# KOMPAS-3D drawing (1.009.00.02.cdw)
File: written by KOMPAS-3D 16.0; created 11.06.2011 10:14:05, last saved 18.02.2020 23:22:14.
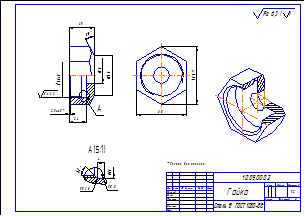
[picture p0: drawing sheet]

Sheet 1: A3, landscape

Title block, sheet 1: name: Гайка; designation: 1.009.00.02; material: Сталь 15  ГОСТ 1050-88; scale: 1:2; sheets: 1; sheet format: A4; stored path: C:\Users\Catonok\Desktop\Гайка.cdw

Views: Вид 1, Вид 2, Вид 3, Спереди 1, Вид по стрелке 4, Вид 7, Вид 8
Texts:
  Catonok
  *Размер для справок.
  Стандартные изделия
  Проточка внутренняя M48x2 У ГОСТ 10549-80
  Ra 3,2
  Ra 6,3
  Ra 6,3 ( )
  TypeKE
  Проточка внутренняя M24x3 У ГОСТ 10549-80
  KTE.LIST=ct.jLYWTfzP..7LCPX8Baa
  ParamsKE
  float
  Без боковой рамки
  Лит-Масса-Масштаб
  Материал-Предприятие
  Масштаб
  Изм.
  Лист
  № докум.
  Подп.
  Дата
  Лит.
  Разраб.
  Пров.
  Т.контр.
  Листов
  Н.контр.
  Утв.
  Изменение
  Номер документа
  Подпись
  Обозначение документа
  Наименование изделия
  Масса изделия по ГОСТ 2.109-73
  Порядковый номер листа
  Общее количество листов в документе
  Характер работы, выполненной лицом, подписавшим документ
  Наименование или индекс предприятия, выпускающего документ
Dimensions and other numbers on the sheet: 59; 4; 0,25; 0,5; 22; 56,3; 2,5; 24; 35; 79,4; 68; 60; 45; 6; 20.7524046; 21.9524046; 1.6; 1; 45.8349364; 46.8349364; 0.5; 1:2; 1.009.00.02; 1.009.00.02-; 2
